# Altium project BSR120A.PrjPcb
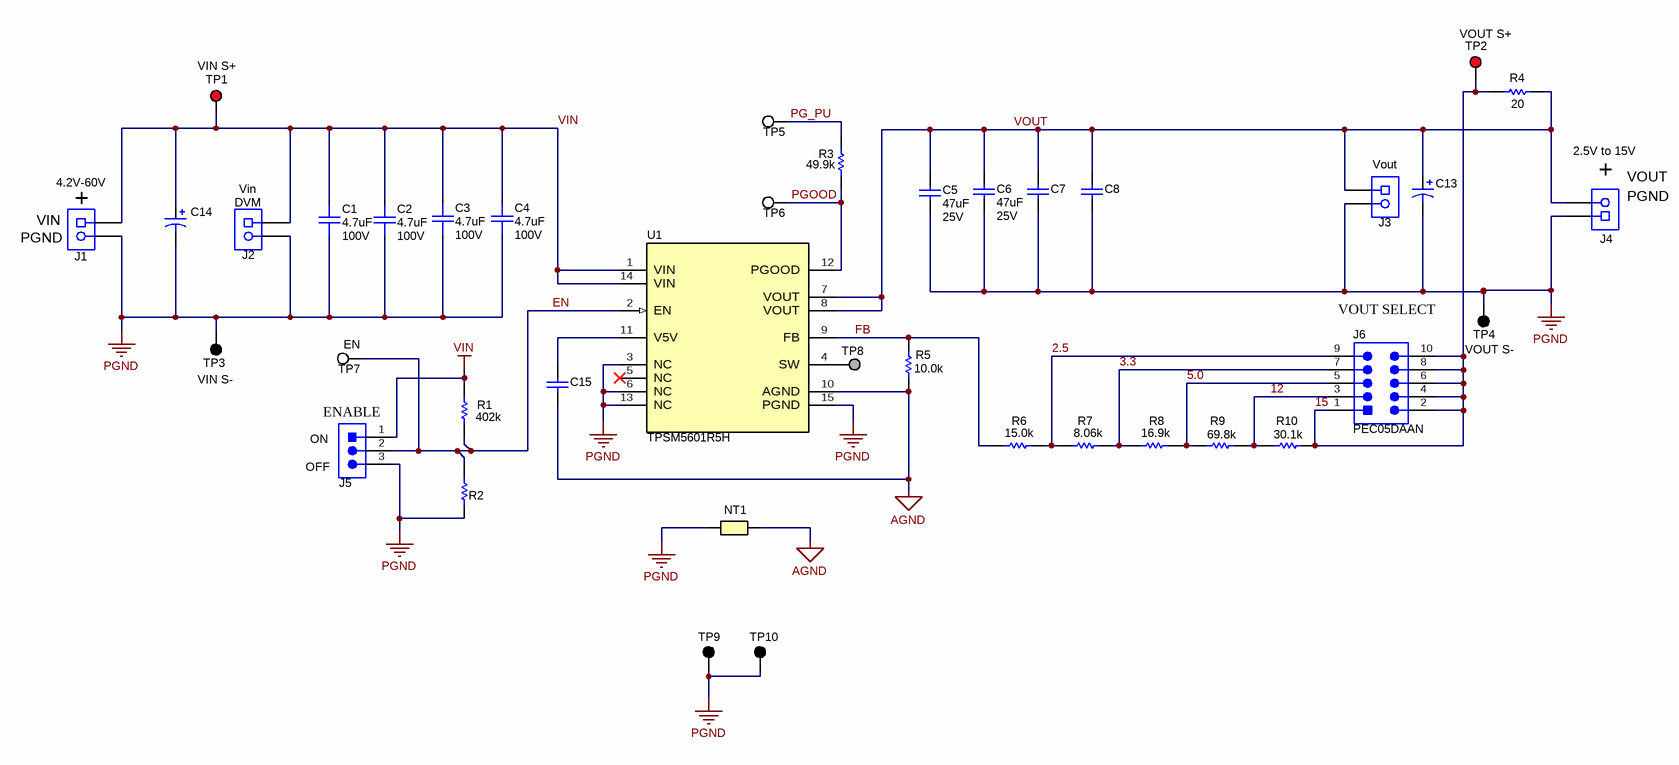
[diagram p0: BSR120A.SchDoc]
CopyrightYear: 2020; EVM_Orderable: TPSM5601R5HEVM; PCB_Layout: J. McTeague; PCB_Rev: A; PRJ_Customer: Public Release; PRJ_Engineer: Jason Arrigo; PRJ_Number: BSR120; PRJ_Title: TPSM5601R5HEVM; SCH_Rev: A; TechSupport: http://www.ti.com/support; TID: N/A
2 sheets, 57 parts. Net scope: global (net labels, ports and power ports of the same name join across sheets).
Board file: BSR120A.PcbDoc
Sheets:
  BSR120A.SchDoc
  BSR120A_Hardware.SchDoc

## Sheet BSR120A.SchDoc: TPSM5601R5EVM schematic
size 431 x 279 mm; REV: A; Date: Not shown in title block; ApprovedBy: Not shown in title block; CheckedBy: Not shown in title block; Author: Not shown in title block; CompanyName: Not shown in title block; DrawnBy: J. McTeague; Engineer: Not shown in title block; Organization: Not shown in title block; Address1: Not shown in title block; Address2: Not shown in title block; Address3: Not shown in title block; Address4: Not shown in title block; DocumentNumber: 1; Revision: Use project parameter SCH_Rev; SheetNumber: 1; SheetTotal: 2; PageSetup: Record=PageOptions¦CenterHorizontal=True¦CenterVertical=True¦PrintScale=1.00¦XCorrection=1.00¦YCorrection=1.00¦PrintKind=0¦BorderSize=5000000¦LeftOffset=0¦BottomOffset=0¦Orientation=2¦PaperLength=1000¦PaperWidth=1000¦Scale=100¦PaperSource=15¦PrintQuality=600¦MediaType=1¦DitherType=10¦PaperKind=Letter¦PrintScaleMode=1

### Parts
C1  ValueDisplayed: 4.7uF  VDC_V: 100V  [FP-GRM31CC72A475KE11L_1206-MFG]  (hidden comment: GRM31CC72A475KE11L)
C2  ValueDisplayed: 4.7uF  VDC_V: 100V  [FP-GRM31CC72A475KE11L_1206-MFG]  (hidden comment: GRM31CC72A475KE11L)
C3  ValueDisplayed: 4.7uF  VDC_V: 100V  [FP-GRM31CC72A475KE11L_1206-MFG]  (hidden comment: GRM31CC72A475KE11L)
C4  ValueDisplayed: 4.7uF  VDC_V: 100V  [FP-GRM31CC72A475KE11L_1206-MFG]  (hidden comment: GRM31CC72A475KE11L)
C5  ValueDisplayed: 47uF  VDC_V: 25V  [1206_190L]  (hidden comment: C3216X5R1E476M160AC)
C6  ValueDisplayed: 47uF  VDC_V: 25V  [1206_190L]  (hidden comment: C3216X5R1E476M160AC)
C7  C3216X5R1E476M160AC  [1206_190L]  (value not drawn)
C8  C3216X5R1E476M160AC  [1206_190L]  (value not drawn)
C13  T520Y337M010ATE035  [7343-40]  (value not drawn)
C14  EEEFT1H470AP  [Panasonic_D]  (value not drawn)
C15  EMK105BJ105KVHF  [0402]  (value not drawn)
J1  OSTTA024163  [On-Shore_OSTTA024163]  (value not drawn)
J2  310-43-102-41-001000  [Mill-max_310-43-102-41-001000]  (value not drawn)
J3  310-43-102-41-001000  [Mill-max_310-43-102-41-001000]  (value not drawn)
J4  OSTTA024163  [On-Shore_OSTTA024163]  (value not drawn)
J5  PEC03SAAN  [CONN_PEC03SAAN]  (value not drawn)
J6  PEC05DAAN  [CONN_PEC05DAAN]
NT1  Net-Tie  [Net-Tie_10mil]  (value not drawn)  (net tie, no BOM)
R1  ValueDisplayed: 402k  [0603]  (hidden comment: CRCW0603402KFKEA)
R2  CRCW0603133KFKEA  [0603]  (value not drawn)
R3  ValueDisplayed: 49.9k  [0603]  (hidden comment: CRCW060349K9FKEA)
R4  ValueDisplayed: 20  [0603]  (hidden comment: CRCW060320R0JNEA)
R5  ValueDisplayed: 10.0k  [0603]  (hidden comment: CRCW060310K0FKEA)
R6  ValueDisplayed: 15.0k  [0603]  (hidden comment: CRCW060315K0FKEA)
R7  ValueDisplayed: 8.06k  [0603]  (hidden comment: CRCW06038K06FKEA)
R8  ValueDisplayed: 16.9k  [0603]  (hidden comment: CRCW060316K9FKEA)
R9  ValueDisplayed: 69.8k  [0603]  (hidden comment: CRCW060369K8FKEA)
R10  ValueDisplayed: 30.1k  [0603]  (hidden comment: CRCW060330K1FKEA)
TP1  5010  [Keystone5010]  (value not drawn)
TP2  5010  [Keystone5010]  (value not drawn)
TP3  5011  [Keystone5011]  (value not drawn)
TP4  5011  [Keystone5011]  (value not drawn)
TP5  5012  [Keystone5012]  (value not drawn)
TP6  5012  [Keystone5012]  (value not drawn)
TP7  5012  [Keystone5012]  (value not drawn)
TP8  TESTPOINT  [TP_25MIL-SMT]  (value not drawn)  (no BOM)
TP9  5011  [Keystone5011]  (value not drawn)
TP10  5011  [Keystone5011]  (value not drawn)
U1  TPSM5601R5H  [RDA0015A-MFG]

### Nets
AGND: C15.2 NT1.1 R5.1 U1.10(AGND)
PGND: C1.1 C2.1 C3.1 C4.1 C5.1 C6.1 C7.1 C8.1 C13.2(-) C14.2(-) J1.2 J2.2 J3.2 J4.1 J5.3 NT1.2 R2.1 TP3.1 TP4.1 TP9.1 TP10.1 U1.3(NC) U1.6(NC) U1.13(NC) U1.15(PGND)
VIN: C1.2 C2.2 C3.2 C4.2 C14.1(+) J1.1 J2.1 J5.1 R1.2 TP1.1 U1.1(VIN) U1.14(VIN)
2.5: J6.9 R6.2 R7.1
3.3: J6.7 R7.2 R8.1
5.0: J6.5 R8.2 R9.1
12: J6.3 R9.2 R10.1
15: J6.1 J6.2 J6.4 J6.6 J6.8 J6.10 R4.2 R10.2 TP2.1
EN: J5.2 R1.1 R2.2 TP7.1 U1.2(EN)
FB: R5.2 R6.1 U1.9(FB)
PG_PU: R3.1 TP5.1
PGOOD: R3.2 TP6.1 U1.12(PGOOD)
VOUT: C5.2 C6.2 C7.2 C8.2 C13.1(+) J3.1 J4.2 R4.1 U1.7(VOUT) U1.8(VOUT)
NetC15_1: C15.1 U1.11(V5V)
NetTP8_1: TP8.1 U1.4(SW)

Not connected (* = marked no-connect by the designer): U1 5(NC)*

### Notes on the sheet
- (near TP2) VOUT S+
- (near TP1) VIN S+
- (near J1) 4.2V-60V
- Vout
- 2.5V to 15V
- (near J1) PGND
- (near J1) VIN
- (near J1) +
- (near J2) Vin
- (near J2) DVM
- (near J4) +
- (near J4) PGND
- (near J4) VOUT
- (near TP3) VIN S-
- (near TP7) EN
- (near J6) VOUT SELECT
- (near TP4) VOUT S-
- (near J5) ON
- (near J5) ENABLE
- (near J5) OFF

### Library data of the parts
C1-C4 = CMP-0089881-1: 4.7µF ±10% 100V Ceramic Capacitor X7S 1206 (3216 Metric); Manufacturer: Murata; TempCo: 22%; SizeZ_mm: 1.9mm; AEC Qualified: No
C5 C6 = CMP-0008656-2: CAP, CERM, 47 uF, 25 V, +/- 20%, X5R, 1206_190; Manufacturer: TDK; Polarized: N; CompType: Capacitor; Value: 47uF; U/M: EA; Cap_F: 47µF; Value1: Unknown; TaMin_C: -55°C; TaMax_C: 85°C; Cap_Case: 1206; SizeArea_mm2: 5.12; SizeAreaWB_mm2: 10.92; SizeX_mm: 3.2; SizeY_mm: 1.6; SizeZ_mm: 1.9; AEC Category: Q200
C7 C8 = CMP-0008656-2: CAP, CERM, 47 uF, 25 V, +/- 20%, X5R, 1206_190; Manufacturer: TDK; Polarized: N; CompType: Capacitor; Value: 47uF; U/M: EA; Cap_F: 47µF; Value1: Unknown; VDC_V: 25V; TaMin_C: -55°C; TaMax_C: 85°C; Cap_Case: 1206; SizeArea_mm2: 5.12; SizeAreaWB_mm2: 10.92; SizeX_mm: 3.2; SizeY_mm: 1.6; SizeZ_mm: 1.9; AEC Category: Q200
C13 = CMP-0064986-2: CAP, Tantalum Polymer, 330 uF, 10 V,+/- 20%, 0.035 ohm, 7343-40 SMD; Manufacturer: Kemet; TaMin_C: -55°C; ESR_ohm: 0.035; Polarized: Y; SizeAreaWB_mm2: 58.59; Value: 330uF; TaMax_C: 105°C; SizeZ_mm: 4; SizeX_mm: 7.3; SizeY_mm: 4.3; Value2: 10V; SizeArea_mm2: 31.39; CompType: Capacitor; AEC Qualified: N; Cap_F: 330µF; AEC Category: Q200
C14 = CMP-0011204-2: CAP, AL, 47 uF, 50 V, +/- 20%, 0.68 ohm, AEC-Q200 Grade 2, SMD; Manufacturer: Panasonic; Polarized: Y; CompType: Capacitor; Value: 47uF; Cap_F: 47µF; VDC_V: 50V; ESR_ohm: 6.8d; IRMS_A: 1.95dA; TaMin_C: -55°C; TaMax_C: 105°C; Cap_Case: 6.3x5.8mm; SizeAreaWB_mm2: 73.96; SizeZ_mm: 6.1; SizeX_mm: 6.6; SizeArea_mm2: 43.56; AEC Grade: 2; AEC Category: Q200; U/M: EA
C15 = CMP-0006347-2: CAP, CERM, 1 uF, 16 V, +/- 10%, X5R, 0402; Manufacturer: Taiyo Yuden; Polarized: N; Value: 1uF; U/M: EA; Cap_F: 1µF; Value1: Unknown; VDC_V: 16V; TaMin_C: -55°C; TaMax_C: 85°C; SizeArea_mm2: 0.5; SizeAreaWB_mm2: 3; SizeX_mm: 1; SizeZ_mm: 0.6; AEC Category: Q200
J1 = CMP-0074959-1: Terminal Block, 2x1, 5.08mm, TH; Manufacturer: On-Shore Technology; CNHeader: False; Green_Lifecycle: Not Set; Green_REACh: Incomplete; CT: True
J2 J3 = CMP-0055017-1: Socket Strip, 2x1, 100mil, Black, Tin, TH; Manufacturer: Mill-Max; CompType: Receptacle; Green_Lifecycle: Active; Green_REACh: Passed; CT: FALSE
J4 = CMP-0074959-1: Terminal Block, 2x1, 5.08mm, TH; Manufacturer: On-Shore Technology; CT: True; Green_REACh: Incomplete; CNHeader: False; Green_Lifecycle: Not Set
J5 = CMP-0002338-1: Header, 100mil, 3x1, Tin, TH; Manufacturer: Sullins Connector Solutions; Pitch_mm: 2.54; Gender: Male; Shrouded: N; Row_Count: 1; Current_A: 3A; Voltage_V: 1.8kV; Cert_UL: Y; Green_Lifecycle: Not Set; Green_REACh: Incomplete; CNHeader: TRUE; CT: FALSE
J6 = CMP-0054550-2: Header, 100mil, 5x2, Tin, TH; Manufacturer: Sullins Connector Solutions; Pitch_mm: 2.54; Gender: Male; Cert_UL: Y; Voltage_V: 1.8kV; Green_REACh: Passed; Current_A: 3A; Shrouded: N; Green_Lifecycle: Active; Row_Count: 2
NT1 = CMP-0078142-3: Single point connection between nets.
R1 = CMP-0022408-4: RES, 402 k, 1%, 0.1 W, AEC-Q200 Grade 0, 0603; Manufacturer: Vishay-Dale; Power_W: 100mW; Value2: 0.1W; VDC_V: 75V; TempCo: 100 ppm/C; EIA_Code: E96; Value: 402k; SizeArea_mm2: 1.28; SizeX_mm: 1.6; SizeY_mm: 0.8; SizeZ_mm: 1; AEC Category: Q200; AEC Qualified: Y; AEC Grade: 0
R2 = CMP-0022038-4: RES, 133 k, 1%, 0.1 W, AEC-Q200 Grade 0, 0603; Manufacturer: Vishay-Dale; Res_ohm: 133k; Power_W: 100mW; Value2: 0.1W; VDC_V: 75V; TempCo: 100 ppm/C; EIA_Code: E96; Value: 133k; SizeArea_mm2: 1.28; SizeX_mm: 1.6; SizeY_mm: 0.8; SizeZ_mm: 1; AEC Category: Q200; AEC Qualified: Y; AEC Grade: 0
R3 = CMP-0022447-4: RES, 49.9 k, 1%, 0.1 W, AEC-Q200 Grade 0, 0603; Manufacturer: Vishay-Dale; CompType: Resistor; Value_Code: 49k9; Power_W: 100mW; Value2: 0.1W; VDC_V: 75V; TempCo: 100 ppm/C; EIA_Code: E96; Value: 49.9k; SizeArea_mm2: 1.28; SizeX_mm: 1.6; SizeY_mm: 0.8; SizeZ_mm: 1; AEC Category: Q200; AEC Qualified: Y; AEC Grade: 0
R4 = CMP-0025754-4: RES, 20, 5%, 0.1 W, AEC-Q200 Grade 0, 0603; Manufacturer: Vishay-Dale; Value: 20; Value_Code: 20R0; Power_W: 100mW; Value2: 0.1W; VDC_V: 75V; TempCo: 200 ppm/C; EIA_Code: E24; SizeArea_mm2: 1.28; SizeX_mm: 1.6; SizeY_mm: 0.8; SizeZ_mm: 1; AEC Category: Q200; AEC Qualified: Y; AEC Grade: 0
R5 = CMP-0021998-4: RES, 10.0 k, 1%, 0.1 W, AEC-Q200 Grade 0, 0603; Manufacturer: Vishay-Dale; Power_W: 100mW; TempCo: 100 ppm/C; Value_Code: 10k0; Value: 10.0k; EIA_Code: E96; Res_ohm: 10k; SizeX_mm: 1.6; SizeY_mm: 0.8; SizeZ_mm: 1; Value2: 0.1W; SizeArea_mm2: 1.28; AEC Qualified: Y; VDC_V: 75V; AEC Category: Q200; AEC Grade: 0
R6 = CMP-0022066-4: RES, 15.0 k, 1%, 0.1 W, AEC-Q200 Grade 0, 0603; Manufacturer: Vishay-Dale; Value: 15.0k; Res_ohm: 15k; Value_Code: 15k0; Power_W: 100mW; Value2: 0.1W; VDC_V: 75V; TempCo: 100 ppm/C; SizeArea_mm2: 1.28; SizeX_mm: 1.6; SizeY_mm: 0.8; SizeZ_mm: 1; EIA_Code: E96; AEC Category: Q200; AEC Qualified: Y; AEC Grade: 0
R7 = CMP-0022634-4: RES, 8.06 k, 1%, 0.1 W, AEC-Q200 Grade 0, 0603; Manufacturer: Vishay-Dale; Value: 8.06k; Value_Code: 8k06; Power_W: 100mW; Value2: 0.1W; VDC_V: 75V; TempCo: 100 ppm/C; SizeArea_mm2: 1.28; SizeX_mm: 1.6; SizeY_mm: 0.8; SizeZ_mm: 1; EIA_Code: E96; AEC Category: Q200; AEC Qualified: Y; AEC Grade: 0
R8 = CMP-0022081-4: RES, 16.9 k, 1%, 0.1 W, AEC-Q200 Grade 0, 0603; Manufacturer: Vishay-Dale; Value: 16.9k; Value_Code: 16k9; Power_W: 100mW; Value2: 0.1W; VDC_V: 75V; TempCo: 100 ppm/C; SizeArea_mm2: 1.28; SizeX_mm: 1.6; SizeY_mm: 0.8; SizeZ_mm: 1; EIA_Code: E96; AEC Category: Q200; AEC Qualified: Y; AEC Grade: 0
R9 = CMP-0022556-4: RES, 69.8 k, 1%, 0.1 W, AEC-Q200 Grade 0, 0603; Manufacturer: Vishay-Dale; Value: 69.8k; Value_Code: 69k8; Power_W: 100mW; Value2: 0.1W; VDC_V: 75V; TempCo: 100 ppm/C; SizeArea_mm2: 1.28; SizeX_mm: 1.6; SizeY_mm: 0.8; SizeZ_mm: 1; EIA_Code: E96; AEC Category: Q200; AEC Qualified: Y; AEC Grade: 0
R10 = CMP-0022324-4: RES, 30.1 k, 1%, 0.1 W, AEC-Q200 Grade 0, 0603; Manufacturer: Vishay-Dale; Value: 30.1k; Value_Code: 30k1; Power_W: 100mW; Value2: 0.1W; VDC_V: 75V; TempCo: 100 ppm/C; SizeArea_mm2: 1.28; SizeX_mm: 1.6; SizeY_mm: 0.8; SizeZ_mm: 1; EIA_Code: E96; AEC Category: Q200; AEC Qualified: Y; AEC Grade: 0
TP1 TP2 = CMP-0055147-1: Test Point, Multipurpose, Red, TH; Manufacturer: Keystone; CNHeader: FALSE; Green_Lifecycle: Active; Green_REACh: Passed; ContactFinish: Silver; CT: TRUE
TP3 = CMP-0055148-1: Test Point, Multipurpose, Black, TH; Manufacturer: Keystone; ContactFinish: Silver; CNHeader: FALSE; CT: TRUE; Green_Lifecycle: Active; Green_REACh: Passed
TP4 TP9 TP10 = CMP-0055148-1: Test Point, Multipurpose, Black, TH; Manufacturer: Keystone; CNHeader: FALSE; Green_Lifecycle: Active; Green_REACh: Passed; ContactFinish: Silver; CT: TRUE
TP5-TP7 = CMP-0055149-1: Test Point, Multipurpose, White, TH; Manufacturer: Keystone; CNHeader: FALSE; Green_Lifecycle: Active; Green_REACh: Passed; ContactFinish: Silver; CT: TRUE
TP8 = CMP-0078143-3: TEST POINT.  No entry in BOM.
U1 = CMP-0088999-2: 60-V Input, 1-V to 16-V Output, 1.5-A Power Module; Manufacturer: Texas Instruments; SizeZ_mm: 4.1mm; TaMin_C: -40°C; TaMax_C: +105°C; Number Of Outputs: 1; Negative Voltage Available: true; Output Type: AdjustableProgrammable; TJmax_C: +125°C; Switching Topology: Buck; Switching Frequency: 1MHz; AEC Qualified: No; CompType: IC; Min Supply Voltage: 4.2V; AEC Category: Q200; Nominal Supply Current: 26uA; Max Supply Voltage: 60V; Output Voltage: 1-16V

## Sheet BSR120A_Hardware.SchDoc
size 431 x 279 mm; Date: Not shown in title block; ApprovedBy: Not shown in title block; CheckedBy: Not shown in title block; Author: Not shown in title block; CompanyName: Not shown in title block; Engineer: Not shown in title block; Organization: Not shown in title block; Address1: Not shown in title block; Address2: Not shown in title block; Address3: Not shown in title block; Address4: Not shown in title block; DocumentNumber: 1; Revision: Use project parameter SCH_Rev; SheetNumber: 2; SheetTotal: 2; PageSetup: Record=PageOptions¦CenterHorizontal=True¦CenterVertical=True¦PrintScale=1.00¦XCorrection=1.00¦YCorrection=1.00¦PrintKind=0¦BorderSize=5000000¦LeftOffset=0¦BottomOffset=0¦Orientation=2¦PaperLength=1000¦PaperWidth=1000¦Scale=100¦PaperSource=15¦PrintQuality=600¦MediaType=1¦DitherType=10¦PaperKind=Letter¦PrintScaleMode=1
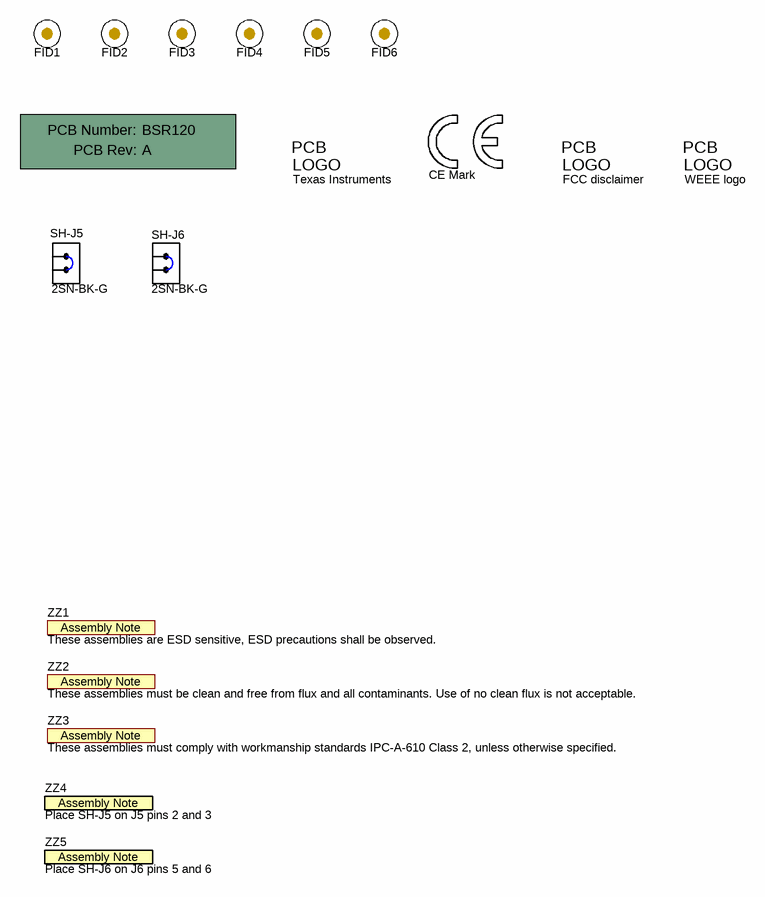
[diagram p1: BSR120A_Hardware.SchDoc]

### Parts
!PCB  Printed Circuit Board  (value not drawn)  (mechanical)
FID1  Fiducial  [Fiducial10-20]  (value not drawn)
FID2  Fiducial  [Fiducial10-20]  (value not drawn)
FID3  Fiducial  [Fiducial10-20]  (value not drawn)
FID4  Fiducial  [Fiducial10-20]  (value not drawn)
FID5  Fiducial  [Fiducial10-20]  (value not drawn)
FID6  Fiducial  [Fiducial10-20]  (value not drawn)
Logo1  Texas Instruments  [TI_Stacked_Overlay_Small]  (no BOM)
Logo2  CE Mark  [CE_Mark_5mm]  (no BOM)
Logo3  FCC disclaimer  [FCC_disclaimer]  (no BOM)
Logo4  WEEE logo  [WEEE_Minimum]  (no BOM)
SH-J5  2SN-BK-G  [2SN-BK-G]
SH-J6  2SN-BK-G  [2SN-BK-G]
ZZ1  These assemblies are ESD sensitive, ESD precautions shall be observed.  [AssemblyNote]  (no BOM)
ZZ2  These assemblies must be clean and free from flux and all contaminants. Use of no clean flux is not acceptable.  [AssemblyNote]  (no BOM)
ZZ3  These assemblies must comply with workmanship standards IPC-A-610 Class 2, unless otherwise specified.  [AssemblyNote]  (no BOM)
ZZ4  Place SH-J5 on J5 pins 2 and 3  [AssemblyNote]  (no BOM)
ZZ5  Place SH-J6 on J6 pins 5 and 6  [AssemblyNote]  (no BOM)

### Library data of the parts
!PCB = CMP-0003618-2: Manufacturer: Any; PartNumber: BSR120
FID1-FID6 = CMP-0077181-1: Fiducial mark.  There is nothing to buy or mount.
Logo1 = CMP-0074838-1: Texas Instrument Corporate Signature; SymbolCreator: a0412235; Lib Reference: TI_Logo; Library Reference: Logo
Logo2 = CMP-0074844-1: SymbolCreator: a0412235
Logo3 = CMP-0074847-1: FCC_disclaimer
Logo4 = CMP-0074769-1
SH-J5 SH-J6 = CMP-0003641-1: Shunt, 2mm, Gold plated, Black; Manufacturer: Samtec; Value: 1x2
ZZ1 = CMP-0077236-1
ZZ2 = CMP-0077237-1
ZZ3 = CMP-0077238-1
ZZ4 ZZ5 = CMP-0003615-1: This Assembly Note will show in the PcbDoc and associated outputs

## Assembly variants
001: not fitted C1 C2 C7 C8 C13 C14 C15 FID1 FID2 FID3 FID4 FID5 FID6 R2 TP8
